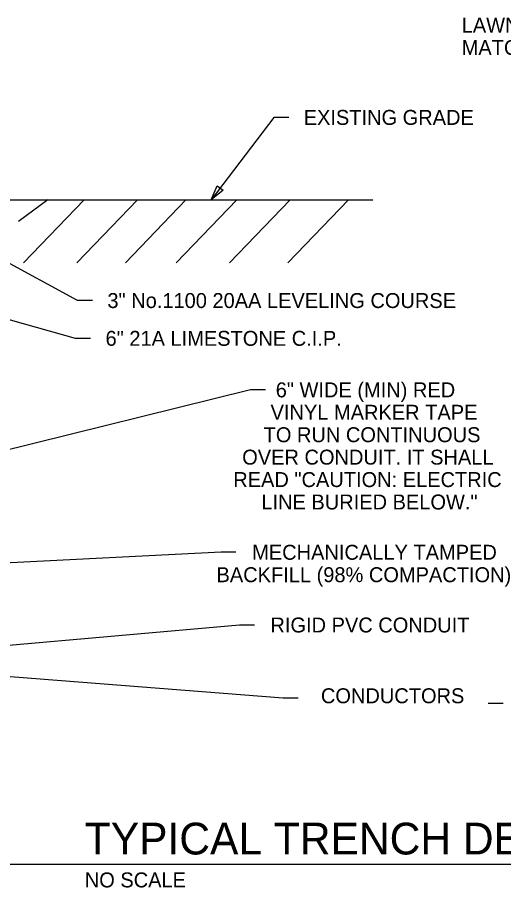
# Model space of a CAD drawing. Extents: x 10310.4 to 10401.1, y 10100.5 to 10143.6.
# Drawn here: x 10338.7 to 10360.35, y 10101.77 to 10140.57 of the extents above; entities that cross this region are included whole.
import ezdxf

# ---------------------------------------------------------------- set-up
doc = ezdxf.new("R2010")
doc.units = 0
for name, color, linetype in [('G-ANNO-TEXT', 7, 'Continuous'), ('G-DETL-LINE', 7, 'Continuous'), ('G-DETL-PATT', 7, 'Continuous')]:
    doc.layers.add(name, color=color, linetype=linetype)

msp = doc.modelspace()

# ---------------------------------------------------------------- linework, layer by layer
at = {"layer": 'G-ANNO-TEXT'}
for p, q in [((10350.118, 10136.112), (10347.327, 10132.437)), ((10350.784, 10136.112), (10350.118, 10136.112)), ((10341.376, 10127.947), (10337.879, 10129.844)), ((10342.043, 10127.947), (10341.376, 10127.947)), ((10341.293, 10126.261), (10336.825, 10127.508)), ((10341.959, 10126.261), (10341.293, 10126.261)), ((10349.089, 10123.964), (10335.433, 10120.592)), ((10349.755, 10123.964), (10349.089, 10123.964)), ((10347.769, 10116.722), (10335.191, 10116.085)), ((10348.436, 10116.722), (10347.769, 10116.722)), ((10348.599, 10113.478), (10333.307, 10112.124)), ((10349.265, 10113.478), (10348.599, 10113.478)), ((10350.535, 10110.217), (10332.93, 10111.596)), ((10351.201, 10110.217), (10350.535, 10110.217)), ((10359.675, 10109.992), (10360.342, 10109.992)), ((10334.547, 10102.814), (10373.072, 10102.814))]:
    msp.add_line(p, q, dxfattribs=at)
msp.add_lwpolyline([(10347.863, 10132.867), (10347.327, 10132.437), (10347.598, 10133.068)], close=True, dxfattribs=at)
at = {"layer": 'G-DETL-LINE'}
msp.add_line((10310.377, 10132.442), (10354.529, 10132.442), dxfattribs=at)
at = {"layer": 'G-DETL-PATT'}
for p, q in [((10340.051, 10132.441), (10338.755, 10131.468)), ((10341.671, 10132.441), (10338.971, 10129.63)), ((10344.048, 10132.441), (10341.347, 10129.63)), ((10346.208, 10132.441), (10343.508, 10129.63)), ((10348.477, 10132.441), (10345.776, 10129.63)), ((10350.853, 10132.441), (10348.152, 10129.63)), ((10353.445, 10132.441), (10350.745, 10129.63))]:
    msp.add_line(p, q, dxfattribs=at)

# ---------------------------------------------------------------- texts
at = {"layer": 'G-ANNO-TEXT'}
for s, height, p in [('LAWN AREA.  GRADE TO', 0.66667, (10358.489, 10139.895)), ('MATCH EXISTING', 0.66667, (10358.489, 10138.895)), ('EXISTING GRADE ', 0.66667, (10351.451, 10135.779)), ('3" No.1100 20AA LEVELING COURSE', 0.66667, (10342.709, 10127.613)), ('6" 21A LIMESTONE C.I.P.', 0.66667, (10342.626, 10125.927)), ('6" WIDE (MIN) RED', 0.66667, (10350.207, 10123.63)), ('VINYL MARKER TAPE', 0.66667, (10349.977, 10122.63)), ('TO RUN CONTINUOUS', 0.66667, (10349.667, 10121.63)), ('OVER CONDUIT. IT SHALL', 0.66667, (10348.713, 10120.63)), ('READ "CAUTION: ELECTRIC', 0.66667, (10348.314, 10119.63)), ('LINE BURIED BELOW."', 0.66667, (10349.566, 10118.63)), ('MECHANICALLY TAMPED', 0.66667, (10349.156, 10116.388)), ('BACKFILL (98% COMPACTION)', 0.66667, (10347.568, 10115.388)), ('RIGID PVC CONDUIT', 0.66667, (10349.97, 10113.145)), ('CONDUCTORS', 0.6667, (10352.219, 10109.99)), ('TYPICAL TRENCH DETAIL', 1.41667, (10341.701, 10103.247)), ('NO SCALE', 0.6667, (10341.701, 10101.779))]:
    msp.add_text(s, height=height, dxfattribs=at).set_placement(p)

doc.saveas('drawing.dxf')
